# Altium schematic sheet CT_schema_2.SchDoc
size 276 x 169 mm
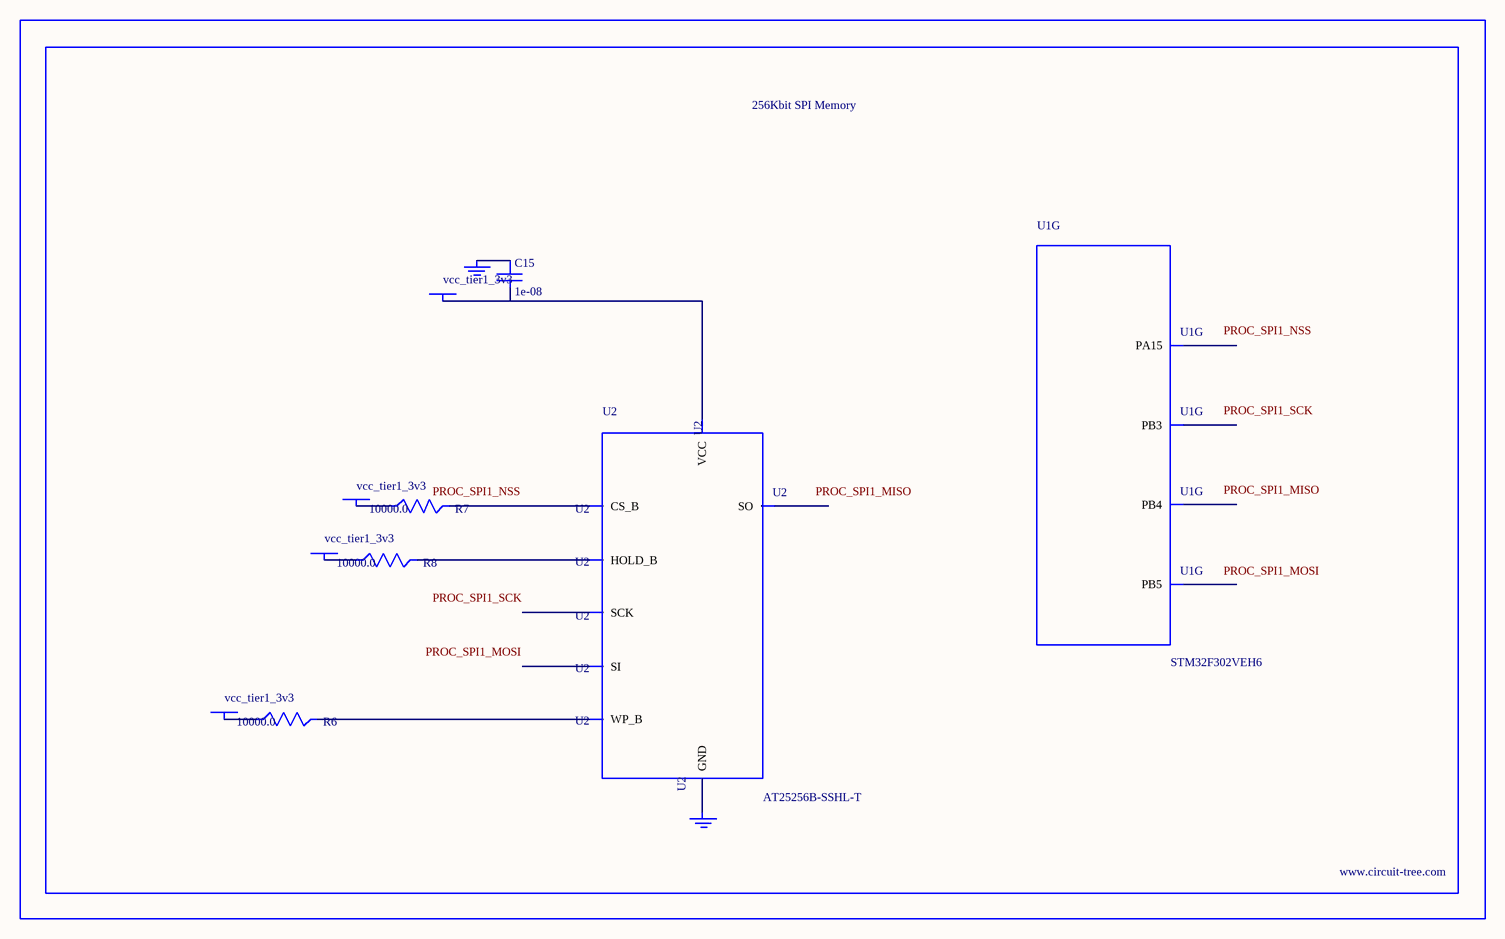
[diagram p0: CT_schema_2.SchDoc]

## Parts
BORDER1  (no value)
C15  1e-08  [C0402]
GND_INSTANCE_1_0  (no value)
GND_INSTANCE_1_1  (no value)
POWER_INSTANCE_1_0  vcc_tier1_3v3
POWER_INSTANCE_1_1  vcc_tier1_3v3
POWER_INSTANCE_1_2  vcc_tier1_3v3
POWER_INSTANCE_1_3  vcc_tier1_3v3
R6  10000.0  [R0603]
R7  10000.0  [R0603]
R8  10000.0  [R0603]
U1  STM32F302VEH6  [UFBGA100]  (part G of 9)
U2  AT25256B-SSHL-T  [SOIC-8]

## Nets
NetC15_1: C15.1 GND_INSTANCE_1_0.0(GND)
NetC15_2: C15.2 POWER_INSTANCE_1_3.0(PWR) U2.8(VCC)
NetGND_INSTANCE_1_1_0: GND_INSTANCE_1_1.0(GND) U2.4(GND)
NetPOWER_INSTANCE_1_0_0: POWER_INSTANCE_1_0.0(PWR) R7.1
NetPOWER_INSTANCE_1_1_0: POWER_INSTANCE_1_1.0(PWR) R6.1
NetPOWER_INSTANCE_1_2_0: POWER_INSTANCE_1_2.0(PWR) R8.1
NetR6_2: R6.2 U2.3(WP_B)
NetR7_2: R7.2 U2.1(CS_B)
NetR8_2: R8.2 U2.7(HOLD_B)

Not connected (* = marked no-connect by the designer): U1 A7(PB4) A8(PB3) A9(PA15) C5(PB5); U2 2(SO) 5(SI) 6(SCK)

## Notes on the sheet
- Labels drawn without touching a wire or pin: PROC_SPI1_MISO, PROC_SPI1_MOSI, PROC_SPI1_NSS, PROC_SPI1_SCK

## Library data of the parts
BORDER1 = BORDER_PAGE1
C15 = C0402C103K3RAC
GND_INSTANCE_1_0 GND_INSTANCE_1_1 = GND
POWER_INSTANCE_1_0-POWER_INSTANCE_1_3 = PWR
R6-R8 = RC0603JR-0710KL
